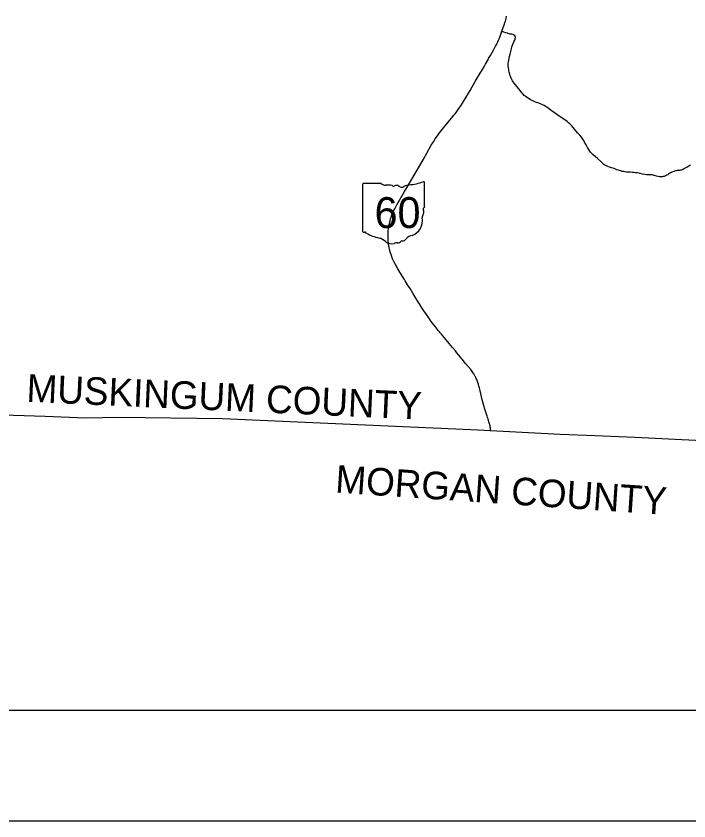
# Model space of a CAD drawing. Extents: x 2015843 to 2287843, y 623733 to 799733.
# Drawn here: x 2136715 to 2161112, y 623733 to 652898 of the extents above; entities that cross this region are included whole.
import ezdxf

# ---------------------------------------------------------------- set-up
doc = ezdxf.new("R2010")
doc.units = 0
for name, color, linetype in [('GM_X_County', 7, 'Continuous'), ('GM_X_County_Text', 7, 'Continuous'), ('GM_X_State_Location', 7, 'Continuous'), ('GM_X_State_Route', 7, 'Continuous'), ('GM_X_State_Shield', 7, 'Continuous'), ('SH_Border', 7, 'Continuous'), ('SH_Cut_Line', 7, 'Continuous')]:
    doc.layers.add(name, color=color, linetype=linetype)

msp = doc.modelspace()

# ---------------------------------------------------------------- linework, layer by layer
at = {"layer": 'GM_X_County'}
msp.add_lwpolyline([(2162797, 637448), (2159165, 637628), (2157707, 637692), (2156444, 637736), (2153917, 637865), (2153458, 637887), (2153202, 637901), (2144198, 638299), (2140461, 638350), (2139229, 638333), (2137764, 638385), (2133924, 638507), (2128723, 638966), (2124973, 639201), (2124024, 639258), (2122789, 639341), (2121522, 639347), (2118235, 639618), (2118221, 639223), (2117677, 639268), (2117476, 639300), (2116823, 639340), (2114403, 639504), (2113002, 639565)], dxfattribs=at)
at = {"layer": 'GM_X_State_Route'}
for points in [[(2153919, 637862), (2153916, 637941), (2153913, 637970), (2153909, 638003), (2153905, 638028), (2153900, 638052), (2153891, 638089), (2153884, 638121), (2153875, 638154), (2153862, 638200), (2153848, 638244), (2153829, 638300), (2153811, 638353), (2153796, 638400), (2153763, 638505), (2153704, 638686), (2153686, 638750), (2153676, 638782), (2153666, 638820), (2153609, 639037), (2153566, 639216), (2153545, 639300), (2153527, 639375), (2153515, 639423), (2153496, 639492), (2153477, 639563), (2153461, 639615), (2153450, 639652), (2153436, 639687), (2153417, 639734), (2153401, 639769), (2153382, 639808), (2153366, 639841), (2153343, 639882), (2153308, 639940), (2153277, 639986), (2153252, 640021), (2153201, 640086), (2153110, 640196), (2153016, 640309), (2152888, 640464), (2152760, 640622), (2152695, 640701), (2152644, 640762), (2152548, 640879), (2152471, 640970), (2152426, 641024), (2152241, 641248), (2152140, 641368), (2152095, 641422), (2152065, 641458), (2152025, 641508), (2151932, 641621), (2151860, 641711), (2151772, 641829), (2151676, 641962), (2151592, 642082), (2151499, 642217), (2151428, 642327), (2151341, 642466), (2151305, 642525), (2151178, 642731), (2151101, 642856), (2150999, 643024), (2150912, 643163), (2150826, 643302), (2150799, 643347), (2150731, 643456), (2150560, 643736), (2150468, 643890), (2150423, 643977), (2150369, 644097), (2150322, 644219), (2150290, 644323), (2150279, 644361), (2150271, 644391), (2150262, 644423), (2150249, 644481), (2150241, 644518), (2150222, 644631), (2150218, 644665), (2150215, 644690), (2150212, 644720), (2150208, 644761), (2150204, 644811), (2150202, 644859), (2150202, 644942), (2150204, 644990), (2150211, 645120), (2150218, 645184), (2150224, 645234), (2150244, 645347), (2150274, 645474), (2150297, 645550), (2150317, 645615), (2150341, 645683), (2150356, 645723), (2150377, 645774), (2150394, 645813), (2150444, 645916), (2150480, 645985), (2150523, 646059), (2150801, 646543), (2150893, 646698), (2151184, 647193), (2151473, 647689), (2151611, 647931), (2151772, 648217), (2151848, 648343), (2151917, 648454), (2151991, 648563), (2152068, 648669), (2152116, 648730), (2152211, 648848), (2152378, 649049), (2152505, 649199), (2152594, 649310), (2152633, 649360), (2152668, 649407), (2152692, 649439), (2152719, 649474), (2152774, 649551), (2152838, 649647), (2152901, 649743), (2153041, 649964), (2153124, 650105), (2153180, 650205), (2153252, 650333), (2153300, 650414), (2153364, 650524), (2153471, 650707), (2153544, 650835), (2153586, 650906), (2153695, 651088), (2153736, 651158), (2153816, 651298), (2153849, 651356), (2153912, 651466), (2154044, 651693), (2154104, 651803), (2154147, 651884), (2154165, 651919), (2154189, 651969), (2154213, 652029), (2154233, 652079), (2154254, 652133), (2154267, 652167), (2154333, 652352), (2154416, 652584), (2154455, 652702), (2154457, 652709), (2154471, 652759), (2154486, 652820), (2154501, 652901)], [(2161166, 647492), (2161045, 647421), (2160957, 647369), (2160913, 647346), (2160868, 647327), (2160837, 647317), (2160802, 647309), (2160778, 647305), (2160754, 647303), (2160720, 647300), (2160681, 647297), (2160652, 647294), (2160620, 647287), (2160593, 647282), (2160562, 647272), (2160532, 647259), (2160489, 647238), (2160447, 647213), (2160377, 647170), (2160343, 647149), (2160304, 647128), (2160259, 647106), (2160218, 647090), (2160183, 647079), (2160151, 647073), (2160115, 647071), (2160078, 647071), (2160043, 647074), (2159998, 647083), (2159940, 647098), (2159821, 647131), (2159777, 647141), (2159746, 647144), (2159706, 647144), (2159652, 647141), (2159603, 647141), (2159572, 647144), (2159508, 647156), (2159435, 647170), (2159339, 647191), (2159243, 647212), (2159179, 647223), (2159114, 647231), (2159065, 647235), (2158983, 647238), (2158934, 647239), (2158852, 647245), (2158787, 647253), (2158738, 647261), (2158690, 647272), (2158643, 647285), (2158564, 647309), (2158502, 647331), (2158396, 647374), (2158303, 647405), (2158229, 647429), (2158168, 647451), (2158122, 647468), (2158091, 647483), (2158061, 647501), (2158032, 647521), (2157993, 647554), (2157922, 647623), (2157801, 647734), (2157727, 647798), (2157626, 647883), (2157589, 647915), (2157566, 647939), (2157544, 647964), (2157515, 648003), (2157481, 648060), (2157439, 648131), (2157384, 648232), (2157329, 648331), (2157296, 648387), (2157260, 648442), (2157212, 648508), (2157151, 648585), (2157078, 648673), (2156917, 648858), (2156851, 648931), (2156794, 648990), (2156758, 649023), (2156733, 649044), (2156694, 649073), (2156572, 649157), (2156411, 649270), (2156278, 649366), (2156119, 649480), (2156026, 649548), (2155955, 649595), (2155911, 649625), (2155867, 649652), (2155829, 649673), (2155782, 649696), (2155726, 649719), (2155674, 649739), (2155549, 649782), (2155473, 649813), (2155423, 649837), (2155372, 649864), (2155316, 649896), (2155261, 649934), (2155209, 649971), (2155143, 650026), (2155091, 650076), (2155053, 650118), (2155013, 650165), (2154942, 650258), (2154874, 650348), (2154777, 650469), (2154744, 650514), (2154719, 650552), (2154692, 650599), (2154669, 650648), (2154653, 650687), (2154636, 650736), (2154617, 650793), (2154597, 650861), (2154586, 650917), (2154577, 650962), (2154567, 651029), (2154562, 651095), (2154561, 651147), (2154564, 651197), (2154569, 651246), (2154580, 651306), (2154608, 651438), (2154626, 651517), (2154651, 651612), (2154677, 651707), (2154697, 651786), (2154716, 651843), (2154740, 651908), (2154766, 651966), (2154795, 652030), (2154807, 652063), (2154814, 652085), (2154817, 652099), (2154819, 652116), (2154819, 652131), (2154816, 652152), (2154813, 652166), (2154805, 652181), (2154798, 652191), (2154789, 652202), (2154777, 652212), (2154766, 652218), (2154752, 652224), (2154735, 652228), (2154688, 652238), (2154635, 652248), (2154561, 652266), (2154533, 652274), (2154468, 652293), (2154403, 652315), (2154364, 652332), (2154333, 652352)]]:
    msp.add_lwpolyline(points, dxfattribs=at)
at = {"layer": 'GM_X_State_Shield'}
for p, q in [((2151520, 645979), (2151520, 646869)), ((2149279, 646798), (2149279, 645097)), ((2149957, 646827), (2149301, 646827)), ((2151520, 645980), (2151520, 645979))]:
    msp.add_line(p, q, dxfattribs=at)
for centre, radius, start, end in [((2150722, 649147), 2377, 275.8445, 288.9065), ((2151495, 646873), 25, 351.8621, 97.738), ((2149305, 646802), 26, 98.1301, 188.1301), ((2150114, 647025), 252, 231.6195, 271.1119), ((2150197, 645872), 904, 80.4867, 94.9883), ((2150402, 646810), 72.7, 219.7921, 297.1024), ((2150509, 646614), 151, 54.4667, 119.1411), ((2150704, 646883), 182, 233.8562, 294.8282), ((2151025, 646308), 478, 97.3462, 120.7689), ((2151610, 645607), 169, 136.8065, 186.9296), ((2151514, 645914), 38.6, 107.944, 210.337), ((2151269, 645802), 232, 340.033, 23.6496), ((2151494, 645976), 26.7, 289.6038, 7.7341), ((2150855, 645494), 595, 292.3089, 8.9858), ((2149305, 645093), 26.2, 171.9584, 258.3066), ((2149309, 645267), 200, 267.339, 280.6039), ((2149350, 644999), 72.1, 29.7484, 93.2717), ((2150260, 646527), 1716, 240.4129, 257.1985), ((2149748, 644332), 537, 47.1842, 75.836), ((2151106, 644619), 326, 94.4031, 142.5768), ((2150329, 644990), 341, 230.7004, 286.2918), ((2150526, 644402), 280, 85.6951, 111.2099), ((2150551, 644863), 182, 268.777, 315.5493), ((2150715, 644698), 51.1, 65.7517, 132.6484), ((2150693, 644932), 192, 282.8732, 323.2771)]:
    msp.add_arc(centre, radius, start, end, dxfattribs=at)
at = {"layer": 'SH_Border'}
msp.add_lwpolyline([(2027843, 795733), (2283843, 795733), (2283843, 627733), (2027843, 627733)], close=True, dxfattribs=at)
at = {"layer": 'SH_Cut_Line'}
msp.add_lwpolyline([(2015843, 623733), (2287843, 623733), (2287843, 799733), (2015843, 799733)], close=True, dxfattribs=at)

# ---------------------------------------------------------------- texts
at = {"layer": 'GM_X_County_Text'}
for s, rotation, p in [('MUSKINGUM COUNTY', 357.4044, (2137078, 638923)), ('MORGAN COUNTY', 356.1283, (2148268, 635634))]:
    msp.add_text(s, height=1000, rotation=rotation, dxfattribs=at).set_placement(p)
at = {"layer": 'GM_X_State_Location'}
for s in ['s', 'r']:
    msp.add_text(s, height=1, dxfattribs=at).set_placement((2150666, 645764))
msp.add_text('60', height=1, rotation=0, dxfattribs=at).set_placement((2150414, 645691))
at = {"layer": 'GM_X_State_Shield'}
msp.add_text('60', height=1120.7, dxfattribs=at).set_placement((2149713, 645217))

doc.saveas('drawing.dxf')
